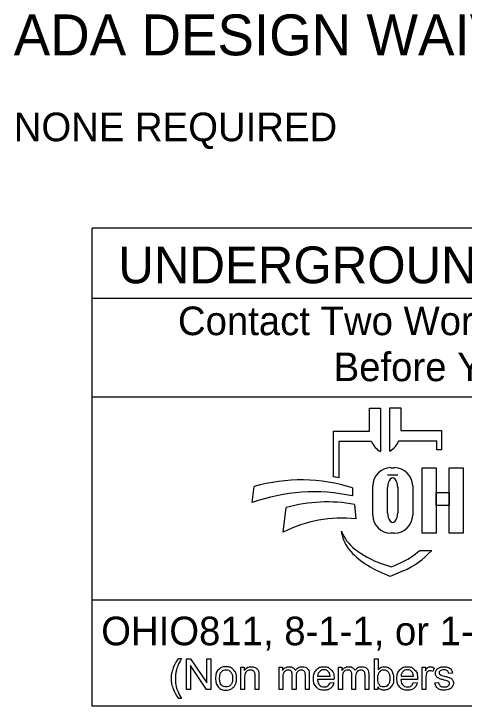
# Model space of a CAD drawing. Extents: x 2.1 to 73.9, y 4 to 26.
# Drawn here: x 41.853 to 44.055, y 6.148 to 9.534 of the extents above; entities that cross this region are included whole.
import ezdxf

# ---------------------------------------------------------------- set-up
doc = ezdxf.new("R2010")
doc.units = 0
doc.layers.add('SH_Data', color=7, linetype='Continuous')
doc.layers.add('SH_Text', color=7, linetype='Continuous')

msp = doc.modelspace()

# ---------------------------------------------------------------- linework, layer by layer
at = {"layer": 'SH_Data'}
for p, q in [((42.236, 6.1479), (42.236, 8.4854)), ((46.486, 8.4854), (42.236, 8.4854)), ((42.236, 8.1438), (46.486, 8.1438)), ((42.236, 7.6604), (46.486, 7.6604)), ((46.486, 6.6658), (42.236, 6.6658)), ((46.486, 6.1479), (42.236, 6.1479))]:
    msp.add_line(p, q, dxfattribs=at)
at = {"layer": 'SH_Text'}
for p, q in [((43.5921, 7.4934), (43.5921, 7.6049)), ((43.5921, 7.6049), (43.6457, 7.6049)), ((43.6457, 7.6049), (43.6457, 7.3928)), ((43.6914, 7.3952), (43.6914, 7.6072)), ((43.6914, 7.6072), (43.745, 7.6072)), ((43.745, 7.6072), (43.745, 7.4957)), ((43.4161, 7.2695), (43.4161, 7.4934)), ((43.4161, 7.4934), (43.5921, 7.4934)), ((43.745, 7.4957), (43.9443, 7.4957)), ((43.9443, 7.4957), (43.9443, 7.4019)), ((43.4414, 7.442), (43.4414, 7.2651)), ((43.6025, 7.442), (43.4414, 7.442)), ((43.921, 7.4443), (43.7346, 7.4443)), ((43.921, 7.4019), (43.921, 7.4443)), ((43.9443, 7.4019), (43.921, 7.4019)), ((43.6971, 7.3142), (43.7136, 7.3142)), ((43.7303, 7.2772), (43.6805, 7.2772)), ((43.0188, 7.1432), (43.0281, 7.2214)), ((43.5094, 7.2149), (43.5094, 7.176)), ((43.6076, 7.0827), (43.6076, 7.2248)), ((43.6805, 7.0941), (43.6805, 7.2165)), ((43.7303, 7.2165), (43.7303, 7.0941)), ((43.8031, 7.2248), (43.8031, 7.0827)), ((43.1706, 6.9987), (43.1853, 7.1188)), ((43.5194, 7.1342), (43.5256, 7.0633)), ((43.4583, 6.9858), (43.4552, 7.0037)), ((43.7136, 6.9933), (43.6971, 6.9933)), ((43.8386, 6.9099), (43.896, 6.9099)), ((43.6401, 6.8495), (43.6996, 6.8291)), ((43.6996, 6.8291), (43.7406, 6.8469)), ((43.7568, 6.8095), (43.6935, 6.782)), ((43.6935, 6.782), (43.6562, 6.7985))]:
    msp.add_line(p, q, dxfattribs=at)
for points in [[(43.8495, 7.3132), (43.9175, 7.3132), (43.9175, 6.9932), (43.8495, 6.9932)], [(43.9816, 7.3132), (44.0496, 7.3132), (44.0496, 6.9932), (43.9816, 6.9932)], [(43.9175, 7.1933), (43.9816, 7.1933), (43.9816, 7.1293), (43.9175, 7.1293)]]:
    msp.add_lwpolyline(points, close=True, dxfattribs=at)
for points in [[(42.6607, 6.3817), (42.6738, 6.3817)], [(42.6974, 6.229), (42.6974, 6.3792), (42.7177, 6.3792), (42.7967, 6.2613), (42.7967, 6.3792), (42.8157, 6.3792), (42.8157, 6.229), (42.7954, 6.229), (42.7164, 6.347), (42.7164, 6.229), (42.6974, 6.229)], [(43.6329, 6.229), (43.6158, 6.229), (43.6158, 6.3792), (43.6342, 6.3792), (43.6342, 6.3257)], [(42.9634, 6.229), (42.9634, 6.3379), (42.98, 6.3379), (42.98, 6.3224)], [(43.1498, 6.229), (43.1498, 6.3379), (43.1663, 6.3379), (43.1663, 6.3225)], [(43.4412, 6.229), (43.4412, 6.3379), (43.4576, 6.3379), (43.4576, 6.3225)], [(43.8489, 6.229), (43.8489, 6.3379), (43.8655, 6.3379), (43.8655, 6.3214)], [(43.908, 6.3344), (43.9015, 6.3173)], [(43.2329, 6.2922), (43.2329, 6.229), (43.2144, 6.229), (43.2144, 6.2997)], [(43.2973, 6.3037), (43.2973, 6.229), (43.2789, 6.229), (43.2789, 6.2975)], [(43.5242, 6.2922), (43.5242, 6.229), (43.5058, 6.229), (43.5058, 6.2997)], [(43.5887, 6.3037), (43.5887, 6.229), (43.5702, 6.229), (43.5702, 6.2975)], [(43.9979, 6.3097), (43.9799, 6.3073)], [(42.9818, 6.2884), (42.9818, 6.229), (42.9634, 6.229)], [(43.0517, 6.2959), (43.0517, 6.229), (43.0333, 6.229), (43.0333, 6.2952)], [(43.1682, 6.2855), (43.1682, 6.229), (43.1498, 6.229)], [(43.4185, 6.2787), (43.3374, 6.2787)], [(43.3384, 6.2938), (43.3992, 6.2938)], [(43.399, 6.2642), (43.418, 6.2618)], [(43.4596, 6.2855), (43.4596, 6.229), (43.4412, 6.229)], [(43.8265, 6.2787), (43.7454, 6.2787)], [(43.7464, 6.2938), (43.8072, 6.2938)], [(43.807, 6.2642), (43.826, 6.2618)], [(43.8674, 6.286), (43.8674, 6.229), (43.8489, 6.229)], [(43.9115, 6.2615), (43.9297, 6.2644)], [(43.6329, 6.2427), (43.6329, 6.229)], [(42.6738, 6.1849), (42.6607, 6.1849)]]:
    msp.add_lwpolyline(points, dxfattribs=at)
for centre, radius, start, end in [((43.6938, 7.4787), 0.0985, 201.9296, 240.7469), ((43.6433, 7.4811), 0.0985, 299.2531, 338.0704), ((43.6971, 7.2248), 0.0895, 90, 180), ((43.7136, 7.2248), 0.0895, 0, 90), ((43.2582, 6.4353), 0.8191, 72.1402, 106.3144), ((43.288, 6.4605), 0.8191, 79.2074, 81.0007), ((43.3213, 6.3042), 0.8919, 77.8238, 109.8274), ((43.3852, 6.4145), 0.7322, 79.44, 105.8467), ((43.6971, 7.0827), 0.0895, 180, 270), ((43.7136, 7.0827), 0.0895, 270, 0), ((43.4572, 6.4313), 0.6357, 83.8248, 116.8021), ((43.6426, 7.0758), 0.2008, 201.0457, 232.5314), ((43.5996, 7.0099), 0.1433, 189.6817, 216.0884), ((43.7332, 7.1073), 0.3088, 216.0884, 235.7167), ((43.8351, 7.327), 0.5173, 232.5314, 241.794), ((43.5972, 7.1773), 0.3602, 293.4582, 312.0712), ((43.5972, 7.1773), 0.401, 293.4582, 317.8286), ((43.8998, 7.3516), 0.6044, 235.7167, 246.2325), ((43.75, 7.1682), 0.3371, 241.794, 250.9821)]:
    msp.add_arc(centre, radius, start, end, dxfattribs=at)
for centre, start_param, end_param in [((43.7054, 7.2165), 4.712389, 7.853982), ((43.7054, 7.0941), 1.570796, 4.712389)]:
    msp.add_ellipse(centre, major_axis=(0, 0.0484), ratio=0.514403, start_param=start_param, end_param=end_param, dxfattribs=at)
for points in [[(42.6607, 6.1849), (42.6454, 6.2041), (42.6348, 6.2299), (42.6243, 6.2557), (42.6243, 6.2834), (42.6243, 6.3078), (42.6322, 6.3301), (42.6414, 6.356), (42.6607, 6.3817)], [(42.6738, 6.3817), (42.6615, 6.3604), (42.6575, 6.3513), (42.6512, 6.3372), (42.6477, 6.3218), (42.6433, 6.3026), (42.6433, 6.2833), (42.6433, 6.234), (42.6738, 6.1849)], [(42.8399, 6.2835), (42.8399, 6.3137), (42.8567, 6.3282), (42.8707, 6.3403), (42.8909, 6.3403), (42.9133, 6.3403), (42.9275, 6.3256), (42.9417, 6.3109), (42.9417, 6.285), (42.9417, 6.264), (42.9354, 6.252), (42.9291, 6.2399), (42.9171, 6.2333), (42.9051, 6.2266), (42.8909, 6.2266), (42.868, 6.2266), (42.854, 6.2413), (42.8399, 6.2559), (42.8399, 6.2835)], [(42.98, 6.3224), (42.9919, 6.3403), (43.0146, 6.3403), (43.0244, 6.3403), (43.0326, 6.3367), (43.0409, 6.3332), (43.045, 6.3275), (43.0491, 6.3217), (43.0507, 6.3139), (43.0517, 6.3087), (43.0517, 6.2959)], [(43.1663, 6.3225), (43.1714, 6.3305), (43.1799, 6.3354), (43.1884, 6.3403), (43.1993, 6.3403), (43.2113, 6.3403), (43.2191, 6.3352), (43.2268, 6.3302), (43.23, 6.3212), (43.2429, 6.3403), (43.2636, 6.3403), (43.2799, 6.3403), (43.2886, 6.3313), (43.2973, 6.3224), (43.2973, 6.3037)], [(43.418, 6.2618), (43.4135, 6.2451), (43.4013, 6.2359), (43.3891, 6.2266), (43.3702, 6.2266), (43.3463, 6.2266), (43.3324, 6.2413), (43.3184, 6.256), (43.3184, 6.2825), (43.3184, 6.31), (43.3325, 6.3251), (43.3466, 6.3403), (43.3692, 6.3403), (43.391, 6.3403), (43.4048, 6.3254), (43.4186, 6.3106), (43.4186, 6.2836), (43.4186, 6.282), (43.4185, 6.2787)], [(43.4576, 6.3225), (43.4628, 6.3305), (43.4713, 6.3354), (43.4798, 6.3403), (43.4906, 6.3403), (43.5027, 6.3403), (43.5105, 6.3352), (43.5182, 6.3302), (43.5214, 6.3212), (43.5343, 6.3403), (43.555, 6.3403), (43.5712, 6.3403), (43.5799, 6.3313), (43.5887, 6.3224), (43.5887, 6.3037)], [(43.6342, 6.3257), (43.6459, 6.3403), (43.664, 6.3403), (43.6741, 6.3403), (43.683, 6.3362), (43.692, 6.3322), (43.6978, 6.3249), (43.7036, 6.3176), (43.7068, 6.3072), (43.7101, 6.2969), (43.7101, 6.2851), (43.7101, 6.2571), (43.6963, 6.2419), (43.6825, 6.2266), (43.6631, 6.2266), (43.6438, 6.2266), (43.6329, 6.2427)], [(43.826, 6.2618), (43.8215, 6.2451), (43.8093, 6.2359), (43.7971, 6.2266), (43.7782, 6.2266), (43.7543, 6.2266), (43.7403, 6.2413), (43.7264, 6.256), (43.7264, 6.2825), (43.7264, 6.31), (43.7405, 6.3251), (43.7546, 6.3403), (43.7772, 6.3403), (43.799, 6.3403), (43.8128, 6.3254), (43.8266, 6.3106), (43.8266, 6.2836), (43.8266, 6.282), (43.8265, 6.2787)], [(43.8655, 6.3214), (43.8719, 6.3329), (43.8772, 6.3366), (43.8826, 6.3403), (43.8891, 6.3403), (43.8984, 6.3403), (43.908, 6.3344)], [(43.9297, 6.2644), (43.9313, 6.2534), (43.9383, 6.2476), (43.9453, 6.2417), (43.958, 6.2417), (43.9707, 6.2417), (43.9769, 6.2469), (43.9831, 6.2521), (43.9831, 6.2591), (43.9831, 6.2653), (43.9776, 6.2689), (43.9738, 6.2714), (43.9587, 6.2752), (43.9384, 6.2803), (43.9306, 6.284), (43.9227, 6.2878), (43.9187, 6.2944), (43.9146, 6.301), (43.9146, 6.309), (43.9146, 6.3162), (43.918, 6.3224), (43.9213, 6.3286), (43.927, 6.3327), (43.9313, 6.3359), (43.9388, 6.3381), (43.9462, 6.3403), (43.9547, 6.3403), (43.9676, 6.3403), (43.9773, 6.3366), (43.987, 6.3329), (43.9916, 6.3266), (43.9962, 6.3203), (43.9979, 6.3097)], [(42.8589, 6.2835), (42.8589, 6.2625), (42.868, 6.2521), (42.8771, 6.2417), (42.8909, 6.2417), (42.9046, 6.2417), (42.9136, 6.2522), (42.9227, 6.2626), (42.9227, 6.2841), (42.9227, 6.3043), (42.9136, 6.3147), (42.9045, 6.3251), (42.8909, 6.3251), (42.8771, 6.3251), (42.868, 6.3147), (42.8589, 6.3044), (42.8589, 6.2835)], [(43.0333, 6.2952), (43.0333, 6.3064), (43.0311, 6.312), (43.029, 6.3176), (43.0235, 6.3209), (43.018, 6.3243), (43.0107, 6.3243), (42.9989, 6.3243), (42.9903, 6.3168), (42.9818, 6.3093), (42.9818, 6.2884)], [(43.2144, 6.2997), (43.2144, 6.312), (43.2099, 6.3181), (43.2054, 6.3243), (43.1952, 6.3243), (43.1874, 6.3243), (43.1808, 6.3202), (43.1741, 6.3161), (43.1712, 6.3082), (43.1682, 6.3003), (43.1682, 6.2855)], [(43.2789, 6.2975), (43.2789, 6.3086), (43.2771, 6.3135), (43.2753, 6.3183), (43.2706, 6.3213), (43.2659, 6.3243), (43.2595, 6.3243), (43.248, 6.3243), (43.2404, 6.3166), (43.2329, 6.309), (43.2329, 6.2922)], [(43.3992, 6.2938), (43.3979, 6.3076), (43.3922, 6.3145), (43.3834, 6.3252), (43.3693, 6.3252), (43.3566, 6.3252), (43.348, 6.3166), (43.3393, 6.3081), (43.3384, 6.2938)], [(43.5058, 6.2997), (43.5058, 6.312), (43.5013, 6.3181), (43.4968, 6.3243), (43.4865, 6.3243), (43.4787, 6.3243), (43.4721, 6.3202), (43.4655, 6.3161), (43.4625, 6.3082), (43.4596, 6.3003), (43.4596, 6.2855)], [(43.5702, 6.2975), (43.5702, 6.3086), (43.5684, 6.3135), (43.5667, 6.3183), (43.5619, 6.3213), (43.5572, 6.3243), (43.5509, 6.3243), (43.5394, 6.3243), (43.5318, 6.3166), (43.5242, 6.309), (43.5242, 6.2922)], [(43.6326, 6.2843), (43.6326, 6.2647), (43.638, 6.256), (43.6466, 6.2417), (43.6615, 6.2417), (43.6735, 6.2417), (43.6823, 6.2522), (43.6911, 6.2628), (43.6911, 6.2836), (43.6911, 6.3049), (43.6827, 6.315), (43.6742, 6.3252), (43.6623, 6.3252), (43.6502, 6.3252), (43.6414, 6.3147), (43.6326, 6.3042), (43.6326, 6.2843)], [(43.8072, 6.2938), (43.8059, 6.3076), (43.8002, 6.3145), (43.7914, 6.3252), (43.7773, 6.3252), (43.7646, 6.3252), (43.756, 6.3166), (43.7473, 6.3081), (43.7464, 6.2938)], [(43.9015, 6.3173), (43.8948, 6.3213), (43.8881, 6.3213), (43.8821, 6.3213), (43.8773, 6.3176), (43.8725, 6.314), (43.8704, 6.3075), (43.8674, 6.2977), (43.8674, 6.286)], [(43.9799, 6.3073), (43.9786, 6.3157), (43.9727, 6.3205), (43.9668, 6.3252), (43.9561, 6.3252), (43.9433, 6.3252), (43.9379, 6.321), (43.9325, 6.3168), (43.9325, 6.3111), (43.9325, 6.3075), (43.9347, 6.3047), (43.937, 6.3017), (43.9418, 6.2997), (43.9446, 6.2987), (43.9581, 6.295), (43.9777, 6.2898), (43.9855, 6.2865), (43.9932, 6.2831), (43.9976, 6.2768), (44.0021, 6.2704), (44.0021, 6.261), (44.0021, 6.2518), (43.9967, 6.2437), (43.9913, 6.2355), (43.9811, 6.2311), (43.971, 6.2266), (43.9581, 6.2266), (43.9369, 6.2266), (43.9257, 6.2354), (43.9146, 6.2442), (43.9115, 6.2615)], [(43.3374, 6.2787), (43.3384, 6.2608), (43.3475, 6.2513), (43.3566, 6.2417), (43.3703, 6.2417), (43.3804, 6.2417), (43.3876, 6.2471), (43.3948, 6.2524), (43.399, 6.2642)], [(43.7454, 6.2787), (43.7464, 6.2608), (43.7555, 6.2513), (43.7646, 6.2417), (43.7783, 6.2417), (43.7884, 6.2417), (43.7956, 6.2471), (43.8028, 6.2524), (43.807, 6.2642)]]:
    msp.add_open_spline(points, degree=3, dxfattribs=at)

# ---------------------------------------------------------------- texts
for s, height, p in [('ADA DESIGN WAIVERS', 0.2, (41.8529, 9.3307)), ('NONE REQUIRED', 0.14, (41.8529, 8.9107)), ('UNDERGROUND UTILITIES', 0.18, (42.3642, 8.2158)), ('Contact Two Working Days', 0.14, (42.6557, 7.9623)), ('Before You Dig', 0.14, (43.4169, 7.7373)), ('OHIO811, 8-1-1, or 1-800-362-2764', 0.14, (42.2805, 6.4457))]:
    msp.add_text(s, height=height, dxfattribs=at).set_placement(p)

doc.saveas('drawing.dxf')
